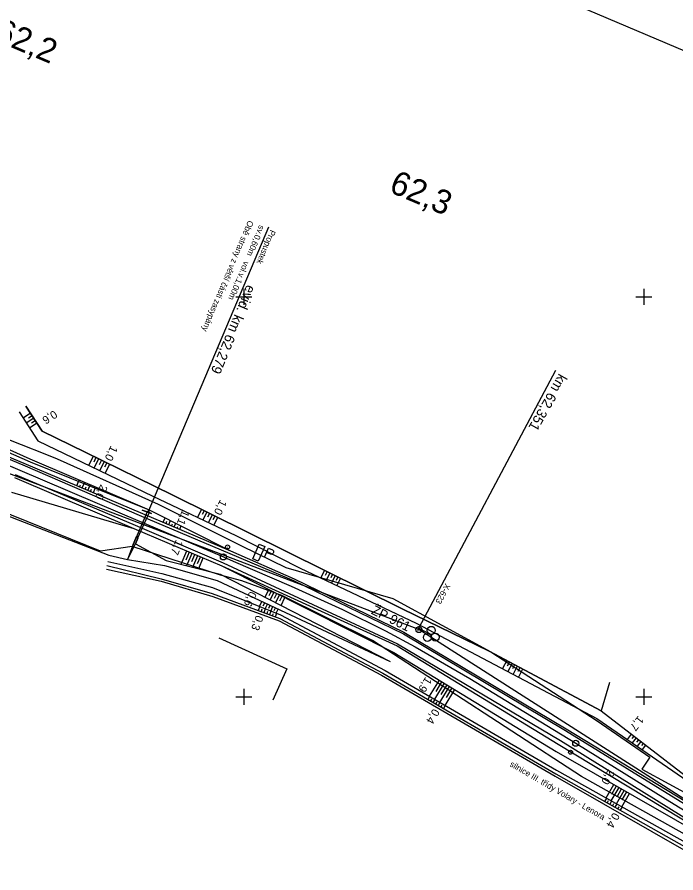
# Model space of a CAD drawing. Extents: x -805636 to -804553, y -1165340 to -1164656.
# Drawn here: x -805256.7 to -805092, y -1165044 to -1164830.1 of the extents above; entities that cross this region are included whole.
import ezdxf

# ---------------------------------------------------------------- set-up
doc = ezdxf.new("R2010")
doc.units = 0
for name, color, linetype in [('0381KM061-064P - Vrstva 1', 7, 'Continuous'), ('0381KM061-064P - Vrstva 17', 7, 'Continuous'), ('0381KM061-064P - Vrstva 19', 7, 'Continuous'), ('0381KM061-064P - Vrstva 23', 7, 'Continuous'), ('0381KM061-064P - Vrstva 33', 7, 'Continuous'), ('0381KM061-064P - Vrstva 4', 7, 'Continuous'), ('0381KM061-064P - Vrstva 48', 7, 'Continuous'), ('0381KM061-064P - Vrstva 49', 7, 'Continuous'), ('0381KM061-064P - Vrstva 51', 7, 'Continuous'), ('0381KM061-064P - Vrstva 7', 7, 'Continuous'), ('0381KM061-064P - Vrstva 8', 7, 'Continuous'), ('formát', 7, 'Continuous'), ('hran DP - hran DP', 7, 'Continuous'), ('krizky_1000 - Vrstva 1', 7, 'Continuous'), ('vyt_sit - polygon', 7, 'Continuous'), ('vyt_sit - stávající', 7, 'Continuous')]:
    doc.layers.add(name, color=color, linetype=linetype)

msp = doc.modelspace()

# ---------------------------------------------------------------- linework, layer by layer
at = {"layer": '0381KM061-064P - Vrstva 1'}
for points in [[(-805344.65, -1164905.78), (-805313.66, -1164918.88), (-805286.17, -1164930.55), (-805256.63, -1164943.09), (-805230.48, -1164954.2), (-805205.12, -1164965.01), (-805202.66, -1164966.06)], [(-805202.66, -1164966.06), (-805188.16, -1164972.33), (-805175.38, -1164978.12)], [(-805175.38, -1164978.12), (-805164.58, -1164983.51), (-805157.2, -1164987.48)], [(-805157.2, -1164987.48), (-805143.51, -1164995.39), (-805131.47, -1165002.7)], [(-805131.47, -1165002.7), (-805117.01, -1165011.6), (-805094.55, -1165025.46), (-805076.19, -1165036.77)]]:
    msp.add_lwpolyline(points, dxfattribs=at)
at = {"layer": '0381KM061-064P - Vrstva 17'}
msp.add_lwpolyline([(-805108.59, -1164996.37), (-805110.66, -1165003.53), (-805138.64, -1164988.6), (-805160.38, -1164977.95), (-805217.98, -1164949.5), (-805239.73, -1164938.85), (-805250.48, -1164933.58), (-805254.52, -1164927.32)], dxfattribs=at)
at = {"layer": '0381KM061-064P - Vrstva 19'}
msp.add_line((-805223.94, -1164953.85), (-805193.79, -1164882.51), dxfattribs=at)
for points in [[(-805224.2, -1164953.73), (-805226.95, -1164960.17)], [(-805223.66, -1164953.94), (-805226.63, -1164960.32)], [(-805225.46, -1164953.29), (-805223.07, -1164954.18)], [(-805223.07, -1164954.18), (-805223.66, -1164953.94), (-805223.66, -1164953.95), (-805224.21, -1164953.74), (-805224.2, -1164953.73), (-805225.46, -1164953.29), (-805225.46, -1164953.29)], [(-805226.95, -1164960.17), (-805227.7, -1164961.91), (-805226.89, -1164959.92)], [(-805226.63, -1164960.32), (-805227.14, -1164961.71), (-805226.51, -1164960.3)], [(-805226.95, -1164960.17), (-805226.89, -1164959.92), (-805226.51, -1164960.3), (-805226.63, -1164960.32)]]:
    msp.add_lwpolyline(points, dxfattribs=at)
at = {"layer": '0381KM061-064P - Vrstva 23'}
msp.add_lwpolyline([(-805206.24, -1164985.26), (-805189.29, -1164992.96), (-805192.75, -1165000.8)], dxfattribs=at)
at = {"layer": '0381KM061-064P - Vrstva 33'}
msp.add_lwpolyline([(-805196.16, -1164961.8), (-805194.79, -1164962.4), (-805196.4, -1164966.09), (-805197.77, -1164965.49)], close=True, dxfattribs=at)
for points in [[(-805194.83, -1164965.11), (-805193.83, -1164962.81)], [(-805193.83, -1164962.81), (-805192.88, -1164963.22)], [(-805193.37, -1164964.36), (-805194.33, -1164963.94)], [(-805192.88, -1164963.22), (-805192.63, -1164963.45), (-805192.59, -1164963.91), (-805192.68, -1164964.11), (-805193.04, -1164964.4), (-805193.37, -1164964.36)]]:
    msp.add_lwpolyline(points, dxfattribs=at)
at = {"layer": '0381KM061-064P - Vrstva 4'}
for points in [[(-805364.7, -1164895.97), (-805343.19, -1164904.86), (-805317.03, -1164915.68), (-805296.75, -1164924.42), (-805284.83, -1164929.56), (-805254.7, -1164942.26), (-805226.16, -1164954.55), (-805203.52, -1164964.18), (-805187.57, -1164970.92)], [(-805364.7, -1164895.97), (-805342.91, -1164904.36), (-805316.81, -1164915.12), (-805296.46, -1164924.13), (-805284.52, -1164929.13), (-805254.45, -1164941.83), (-805225.92, -1164953.93), (-805203.38, -1164963.47), (-805187.4, -1164970.45)], [(-805257.4, -1164945.18), (-805227.5, -1164957.9), (-805205.55, -1164967.2), (-805161.7, -1164987.26), (-805121.4, -1165011.84), (-805082.08, -1165035.58)], [(-805257.21, -1164944.39), (-805227.21, -1164957.06), (-805205.17, -1164966.48), (-805161.59, -1164986.72), (-805120.84, -1165010.88), (-805082.03, -1165034.98)], [(-805187.57, -1164970.92), (-805160.12, -1164984.24), (-805119.58, -1165008.37), (-805080.47, -1165032.5)], [(-805187.4, -1164970.45), (-805159.98, -1164983.82), (-805119.44, -1165007.96), (-805080.11, -1165031.8)]]:
    msp.add_lwpolyline(points, dxfattribs=at)
at = {"layer": '0381KM061-064P - Vrstva 48'}
for p, q in [((-805253.38, -1164929.09), (-805255.23, -1164930.29)), ((-805252.57, -1164930.35), (-805254.41, -1164931.54)), ((-805252.97, -1164929.72), (-805253.9, -1164930.32)), ((-805251.75, -1164931.61), (-805253.59, -1164932.8)), ((-805252.16, -1164930.99), (-805253.08, -1164931.58)), ((-805237.68, -1164939.86), (-805238.76, -1164942.09)), ((-805237, -1164940.19), (-805237.55, -1164941.3)), ((-805236.33, -1164940.52), (-805237.41, -1164942.74)), ((-805235.65, -1164940.85), (-805236.2, -1164941.96)), ((-805234.98, -1164941.18), (-805236.06, -1164943.39)), ((-805234.31, -1164941.51), (-805234.85, -1164942.61)), ((-805233.63, -1164941.84), (-805234.71, -1164944.04)), ((-805241.16, -1164945.74), (-805241.33, -1164946.13)), ((-805241.79, -1164947.2), (-805241.34, -1164946.12)), ((-805241.1, -1164947.49), (-805240.87, -1164946.95)), ((-805240.47, -1164946.04), (-805240.55, -1164946.22)), ((-805240.41, -1164947.78), (-805239.95, -1164946.69)), ((-805239.78, -1164946.33), (-805239.94, -1164946.69)), ((-805239.72, -1164948.07), (-805239.48, -1164947.52)), ((-805239.09, -1164946.63), (-805239.17, -1164946.8)), ((-805239.03, -1164948.37), (-805238.55, -1164947.25)), ((-805238.4, -1164946.93), (-805238.54, -1164947.25)), ((-805237.71, -1164947.22), (-805237.78, -1164947.38)), ((-805237.65, -1164948.95), (-805237.16, -1164947.8)), ((-805237.03, -1164947.52), (-805237.15, -1164947.81)), ((-805238.34, -1164948.66), (-805238.1, -1164948.09)), ((-805210.62, -1164953.13), (-805211.59, -1164955.1)), ((-805209.95, -1164953.46), (-805210.43, -1164954.44)), ((-805209.27, -1164953.79), (-805210.24, -1164955.75)), ((-805208.6, -1164954.13), (-805209.08, -1164955.1)), ((-805220.17, -1164956.36), (-805219.7, -1164955.24)), ((-805219.48, -1164956.65), (-805219.26, -1164956.11)), ((-805218.79, -1164956.94), (-805218.36, -1164955.91)), ((-805207.93, -1164954.46), (-805208.88, -1164956.39)), ((-805207.26, -1164954.79), (-805207.73, -1164955.75)), ((-805206.58, -1164955.12), (-805207.53, -1164957.04)), ((-805218.1, -1164957.23), (-805217.89, -1164956.74)), ((-805217.41, -1164957.53), (-805217.02, -1164956.59)), ((-805216.72, -1164957.82), (-805216.53, -1164957.37)), ((-805216.03, -1164958.11), (-805215.67, -1164957.27)), ((-805215.72, -1164966.81), (-805214.31, -1164963.49)), ((-805214.44, -1164965.71), (-805213.62, -1164963.78)), ((-805214.25, -1164967.18), (-805212.93, -1164964.07)), ((-805213, -1164966.17), (-805212.24, -1164964.37)), ((-805212.78, -1164967.55), (-805211.55, -1164964.66)), ((-805211.57, -1164966.63), (-805210.86, -1164964.95)), ((-805211.31, -1164967.93), (-805210.17, -1164965.24)), ((-805179.84, -1164968.33), (-805180.79, -1164970.25)), ((-805179.17, -1164968.67), (-805179.64, -1164969.62)), ((-805178.5, -1164969), (-805179.43, -1164970.9)), ((-805177.82, -1164969.33), (-805178.29, -1164970.27)), ((-805177.15, -1164969.66), (-805178.08, -1164971.54)), ((-805176.48, -1164970), (-805176.94, -1164970.93)), ((-805175.81, -1164970.33), (-805176.72, -1164972.18)), ((-805194.72, -1164975.07), (-805193.75, -1164973.14)), ((-805193.67, -1164974.64), (-805193.08, -1164973.48)), ((-805193.39, -1164975.75), (-805192.41, -1164973.81)), ((-805192.33, -1164975.32), (-805191.74, -1164974.15)), ((-805192.05, -1164976.44), (-805191.07, -1164974.49)), ((-805190.99, -1164976), (-805190.4, -1164974.83)), ((-805190.72, -1164977.12), (-805189.73, -1164975.16)), ((-805196.04, -1164977.44), (-805196.4, -1164978.43)), ((-805196.08, -1164977.43), (-805195.48, -1164976.15)), ((-805195.15, -1164977.21), (-805194.8, -1164976.47)), ((-805194.69, -1164977.99), (-805194.12, -1164976.79)), ((-805193.77, -1164977.8), (-805193.45, -1164977.11)), ((-805193.29, -1164978.55), (-805192.77, -1164977.42)), ((-805192.39, -1164978.4), (-805192.09, -1164977.74)), ((-805195.48, -1164978.11), (-805195.7, -1164978.69)), ((-805194.65, -1164978), (-805194.99, -1164978.95)), ((-805194.09, -1164978.65), (-805194.29, -1164979.21)), ((-805193.25, -1164978.56), (-805193.59, -1164979.47)), ((-805192.69, -1164979.2), (-805192.89, -1164979.73)), ((-805191.86, -1164979.13), (-805192.18, -1164979.99)), ((-805191.9, -1164979.11), (-805191.41, -1164978.06)), ((-805134.27, -1164990.93), (-805135.34, -1164992.94)), ((-805133.61, -1164991.28), (-805134.14, -1164992.29)), ((-805132.95, -1164991.64), (-805134.02, -1164993.64)), ((-805132.29, -1164991.99), (-805132.82, -1164992.99)), ((-805131.62, -1164992.34), (-805132.69, -1164994.34)), ((-805130.96, -1164992.7), (-805131.49, -1164993.69)), ((-805130.3, -1164993.05), (-805131.36, -1164995.04)), ((-805153.57, -1164999.86), (-805151.11, -1164995.82)), ((-805152.28, -1165000.61), (-805149.83, -1164996.6)), ((-805151.94, -1164998.63), (-805150.47, -1164996.21)), ((-805150.65, -1164999.39), (-805149.19, -1164996.99)), ((-805150.98, -1165001.37), (-805148.55, -1164997.38)), ((-805149.69, -1165002.12), (-805147.27, -1164998.16)), ((-805149.36, -1165000.16), (-805147.91, -1164997.77)), ((-805153.56, -1164999.87), (-805154, -1165000.63)), ((-805153.09, -1165000.55), (-805153.35, -1165001.01)), ((-805152.27, -1165000.62), (-805152.71, -1165001.38)), ((-805151.79, -1165001.3), (-805152.06, -1165001.76)), ((-805150.97, -1165001.38), (-805151.41, -1165002.14)), ((-805150.5, -1165002.06), (-805150.76, -1165002.51)), ((-805149.67, -1165002.13), (-805150.11, -1165002.89)), ((-805103.12, -1165009.34), (-805104.11, -1165010.63)), ((-805102.52, -1165009.79), (-805103.01, -1165010.42)), ((-805101.93, -1165010.25), (-805102.87, -1165011.48)), ((-805101.33, -1165010.71), (-805101.8, -1165011.31)), ((-805100.74, -1165011.17), (-805101.64, -1165012.33)), ((-805100.14, -1165011.62), (-805100.58, -1165012.19)), ((-805099.55, -1165012.08), (-805100.4, -1165013.19)), ((-805109.42, -1165025.28), (-805107.48, -1165021.9)), ((-805108.11, -1165026.01), (-805106.18, -1165022.64)), ((-805107.99, -1165024.3), (-805106.83, -1165022.27)), ((-805106.8, -1165026.74), (-805104.88, -1165023.39)), ((-805106.69, -1165025.03), (-805105.53, -1165023.01)), ((-805105.49, -1165027.48), (-805103.58, -1165024.13)), ((-805105.38, -1165025.77), (-805104.23, -1165023.76)), ((-805109.35, -1165025.32), (-805109.81, -1165026.13)), ((-805108.88, -1165026.01), (-805109.15, -1165026.5)), ((-805108.04, -1165026.05), (-805108.5, -1165026.86)), ((-805107.57, -1165026.74), (-805107.85, -1165027.23)), ((-805106.73, -1165026.78), (-805107.2, -1165027.6)), ((-805106.27, -1165027.48), (-805106.54, -1165027.97)), ((-805105.42, -1165027.51), (-805105.89, -1165028.34))]:
    msp.add_line(p, q, dxfattribs=at)
at = {"layer": '0381KM061-064P - Vrstva 49'}
for p, q in [((-805225.92, -1164953.93), (-805203.38, -1164963.47)), ((-805227.5, -1164957.9), (-805205.55, -1164967.2))]:
    msp.add_line(p, q, dxfattribs=at)
for points in [[(-805295.19, -1164922.01), (-805283.65, -1164926.95), (-805253.5, -1164940.46), (-805223.68, -1164953.23)], [(-805296.46, -1164924.13), (-805284.52, -1164929.13), (-805254.45, -1164941.83), (-805225.92, -1164953.93)], [(-805295.94, -1164922.85), (-805284.04, -1164927.86), (-805253.46, -1164941.25), (-805223.68, -1164953.23)], [(-805254.52, -1164927.32), (-805250.48, -1164933.58), (-805239.73, -1164938.85), (-805217.98, -1164949.5), (-805160.38, -1164977.95), (-805138.64, -1164988.6), (-805110.66, -1165003.53), (-805077.76, -1165028.83)], [(-805256.22, -1164928.77), (-805251.54, -1164935.95), (-805222.74, -1164949.79)], [(-805258.14, -1164948.79), (-805227.5, -1164957.9)], [(-805222.74, -1164949.79), (-805202.04, -1164959.65), (-805185.93, -1164967.81)], [(-805223.66, -1164953.94), (-805223.07, -1164954.18), (-805225.46, -1164953.29), (-805225.46, -1164953.29), (-805224.2, -1164953.73)], [(-805223.66, -1164953.94), (-805223.68, -1164953.23), (-805224.2, -1164953.73)], [(-805223.68, -1164953.23), (-805203.38, -1164963.47)], [(-805259.86, -1164954.37), (-805233.78, -1164964.57)], [(-805227.7, -1164961.91), (-805226.89, -1164959.92), (-805226.51, -1164960.3), (-805227.14, -1164961.71)], [(-805227.7, -1164961.91), (-805229.15, -1164965.65), (-805227.14, -1164961.71)], [(-805227.14, -1164961.71), (-805219.41, -1164965.87), (-805205.96, -1164969.29)], [(-805233.78, -1164964.57), (-805229.15, -1164965.65)], [(-805234.06, -1164966.19), (-805220.55, -1164969.15), (-805207.89, -1164972.65), (-805190.88, -1164979.53), (-805164.65, -1164993.41), (-805121.85, -1165018.34), (-805084.74, -1165039.06)], [(-805229.15, -1164965.65), (-805219.86, -1164967.18), (-805206.69, -1164970.91), (-805163.45, -1164991.14)], [(-805234.27, -1164967.17), (-805220.67, -1164970.52), (-805207.94, -1164974.16), (-805191.02, -1164980.42), (-805165.29, -1164994.07), (-805122, -1165019.23), (-805085.43, -1165039.91)], [(-805205.96, -1164969.29), (-805163.45, -1164991.14)], [(-805205.55, -1164967.2), (-805162.48, -1164988.88), (-805121.89, -1165013.64), (-805082.35, -1165036.29)], [(-805185.93, -1164967.81), (-805156.92, -1164981.59), (-805111.71, -1165005.38), (-805077.76, -1165028.83)]]:
    msp.add_lwpolyline(points, dxfattribs=at)
at = {"layer": '0381KM061-064P - Vrstva 51'}
msp.add_lwpolyline([(-805234.38, -1164968.09), (-805220.73, -1164971.11), (-805207.78, -1164974.89), (-805191.18, -1164980.95), (-805165.61, -1164994.58), (-805122.14, -1165019.85), (-805085.93, -1165040.55)], dxfattribs=at)
at = {"layer": '0381KM061-064P - Vrstva 7'}
for p, q in [((-805204.14, -1164962.5), (-805204.05, -1164962.54)), ((-805118.35, -1165013.81), (-805118.26, -1165013.86))]:
    msp.add_line(p, q, dxfattribs=at)
for centre, radius in [((-805204.09, -1164962.52), 0.5), ((-805205.12, -1164965.01), 0.75), ((-805117.01, -1165011.6), 0.75), ((-805118.3, -1165013.84), 0.5)]:
    msp.add_circle(centre, radius, dxfattribs=at)
at = {"layer": '0381KM061-064P - Vrstva 8'}
for p, q in [((-805156.26, -1164982.82), (-805122, -1164918.34)), ((-805155.9, -1164982.16), (-805156.62, -1164983.48)), ((-805156.26, -1164982.82), (-805153.62, -1164984.25))]:
    msp.add_line(p, q, dxfattribs=at)
for centre in [(-805154.1, -1164985.13), (-805153.15, -1164983.37), (-805152.13, -1164985.06)]:
    msp.add_circle(centre, 1, dxfattribs=at)
at = {"layer": 'formát'}
msp.add_line((-804939.6, -1164902.47), (-805519.31, -1164655.82), dxfattribs=at)
at = {"layer": 'hran DP - hran DP'}
for p, q in [((-805367.78, -1164893.1), (-805249.75, -1164939.24)), ((-805249.75, -1164939.24), (-805246.66, -1164940.48)), ((-805246.66, -1164940.48), (-805221.45, -1164951.84)), ((-805235.86, -1164963.58), (-805268.35, -1164950.48)), ((-805221.45, -1164951.84), (-805200.57, -1164962.2)), ((-805227.98, -1164962.4), (-805235.86, -1164963.58)), ((-805205.81, -1164969.6), (-805227.98, -1164962.4)), ((-805200.57, -1164962.2), (-805189.53, -1164967.68)), ((-805189.53, -1164967.68), (-805162.72, -1164975.42)), ((-805200.52, -1164970.95), (-805205.81, -1164969.6)), ((-805190.48, -1164974.63), (-805200.52, -1164970.95)), ((-805167.83, -1164985.89), (-805190.48, -1164974.63)), ((-805162.72, -1164975.42), (-805138.24, -1164988.78)), ((-805115.56, -1165019.91), (-805167.83, -1164985.89)), ((-805138.24, -1164988.78), (-805111.69, -1165006.01)), ((-805111.69, -1165006.01), (-805098.46, -1165015.06)), ((-805098.46, -1165015.06), (-805100.45, -1165018.04)), ((-805100.45, -1165018.04), (-805061.96, -1165039.19)), ((-805085.48, -1165036.81), (-805115.56, -1165019.91))]:
    msp.add_line(p, q, dxfattribs=at)
at = {"layer": 'krizky_1000 - Vrstva 1'}
for points in [[(-805200, -1164898), (-805200, -1164902)], [(-805100, -1164898), (-805100, -1164902)], [(-805202, -1164900), (-805198, -1164900)], [(-805102, -1164900), (-805098, -1164900)], [(-805200, -1164998), (-805200, -1165002)], [(-805100, -1164998), (-805100, -1165002)], [(-805202, -1165000), (-805198, -1165000)], [(-805102, -1165000), (-805098, -1165000)]]:
    msp.add_lwpolyline(points, dxfattribs=at)
at = {"layer": 'vyt_sit - polygon'}
for p, q in [((-805156.24, -1164983.18), (-805286.72, -1164933.58)), ((-805011.29, -1165075.75), (-805156.24, -1164983.18))]:
    msp.add_line(p, q, dxfattribs=at)
at = {"layer": 'vyt_sit - stávající'}
msp.add_line((-805156.29, -1164983.15), (-805156.2, -1164983.2), dxfattribs=at)
msp.add_circle((-805156.24, -1164983.18), 0.756, dxfattribs=at)

# ---------------------------------------------------------------- texts
at = {"layer": '0381KM061-064P - Vrstva 19'}
for s, height, rotation, p in [('Obě strany z větší části zasypány', 1.5, 247.0922, (-805198.9, -1164880.77)), ('sv.0,60m   vol.v.1,00m', 1.5, 247.0922, (-805196.13, -1164881.94)), ('Propustek', 1.5, 247.0922, (-805193.37, -1164883.11)), ('evid. km 62,279', 2.5, 247.4086, (-805199.25, -1164896.81))]:
    msp.add_text(s, height=height, rotation=rotation, dxfattribs=at).set_placement(p)
at = {"layer": '0381KM061-064P - Vrstva 48'}
for s, rotation, p in [('0,6', 212.8254, (-805247.5, -1164928.26)), ('1,0', 243.9354, (-805233.24, -1164937.05)), ('2,0', 247.0311, (-805235.82, -1164946.75)), ('1,0', 243.7126, (-805205.92, -1164950.56)), ('1,1', 247.0544, (-805215.37, -1164953.11)), ('1,7', 247.0407, (-805216.94, -1164960.55)), ('0,6', 244.9302, (-805198.51, -1164973.47)), ('0,3', 249.7019, (-805196.93, -1164979.45)), ('1,9', 238.6155, (-805154.54, -1164994.87)), ('0,4', 239.8316, (-805152.65, -1165002.8)), ('1,7', 232.4407, (-805101.35, -1165004.58)), ('2,0', 240.1974, (-805108.86, -1165017.97)), ('0,4', 240.5094, (-805107.62, -1165028.78))]:
    msp.add_text(s, height=2, rotation=rotation, dxfattribs=at).set_placement(p)
at = {"layer": '0381KM061-064P - Vrstva 51'}
msp.add_text('silnice III. třídy Volary - Lenora', height=1.5, rotation=329.8239, dxfattribs=at).set_placement((-805133.64, -1165017.24))
at = {"layer": '0381KM061-064P - Vrstva 7'}
for s, rotation, p in [('62,2', 337.0034, (-805262.71, -1164835.71)), ('62,3', 336.9207, (-805163.97, -1164873.65))]:
    msp.add_text(s, height=6, rotation=rotation, dxfattribs=at).set_placement(p)
at = {"layer": '0381KM061-064P - Vrstva 8'}
for s, height, rotation, p in [('km 62,351', 2.5, 240.4167, (-805121.2, -1164919.01)), ('X-623', 1.5, 241.514, (-805149.6, -1164971.53))]:
    msp.add_text(s, height=height, rotation=rotation, dxfattribs=at).set_placement(p)
at = {"layer": 'vyt_sit - stávající'}
msp.add_text('ŽP 961', height=2.4, rotation=333.5611, dxfattribs=at).set_placement((-805168.35, -1164979.13))

doc.saveas('drawing.dxf')
